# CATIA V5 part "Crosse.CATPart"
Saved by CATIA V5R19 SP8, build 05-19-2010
Part number: Part2
Bounding box of the stored display mesh (mm): x -6.372 to 6.628, y -5 to 5, z -3.329 to 3.329
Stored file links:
  F:\Projet3\Crosse.CATPart
  F:\Projet3\Produit1.CATProduct
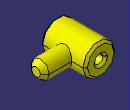
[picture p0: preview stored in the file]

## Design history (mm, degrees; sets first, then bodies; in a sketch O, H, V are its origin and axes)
Parameters
  Longueur = 10 mm
Body1 (main body)
  Sketch1 on yz-plane, origin (0, 0, 0), H (0, 1, 0), V (0, 0, 1)
    circle A1 centre (0, 0) radius 2
    radius A1 = 2 {= Longueur *0.2}
  Pad1: profile Sketch1, direction (1, 0, 0), length 6.628 {= Longueur *0.6628}
  Chamfer1: length 1 {= Longueur *0.1}, angle 45, on edge [face of Pad1 from Sketch1.A1 | end face of Pad1]
  Sketch2 on zx-plane, origin (0, 0, 0), H (-1, 0, 0), V (0, 0, 1)
    arc A1 centre (2.8723, 0) radius 3.5 from (0, 2) to (0, -2) ccw
    point P2 (-0.6277, 0)
    point P3 (0, 2)
    point P4 (0, -2)
    reference projected line E1 (0, -2) -> (0, 2) from edge [start face of Pad1 | face of Pad1 from Sketch1.A1]
    reference projected line E2 (0, -2) -> (0, 2) from edge [start face of Pad1 | face of Pad1 from Sketch1.A1]
    distance P3 P4 = 4 {= Longueur *0.4}
    distance P4 H = 2 {= Longueur *0.2}
    radius A1 = 3.5 {= Longueur *0.35}
    coincidence: A1 P2, P2 H, P3 E1, P4 E2
  Pocket1: profile Sketch2, direction (0, -1, 0), length 8 {= Longueur *0.8}, mirrored extent
  Point1: (0 {= Longueur *0}, 5 {= Longueur *0.5}, 0 {= Longueur *0})
  Plane1: type OffsetPt, RefPlane zx-plane, RefPoint Point1
  Sketch3 on Plane1, origin (0, 5, 0), H (-1, 0, 0), V (0, 0, 1)
    circle A1 centre (2.8723, 0) radius 3.5
    reference projected arc E1 centre (2.8723, 0) radius 3.5 from (0, 2) to (0, -2) ccw from edge [face of Pad1 from Sketch1.A1 | face of Pocket1 from Sketch2.A1]
    coincidence: A1 E1
  Pad2: profile Sketch3, direction (0, -1, 0), length 10 {= Longueur *1}
  Sketch4 on start face of Pad2, origin (0, 5, 0), H (-1, 0, 0), V (0, 0, 1)
    circle A1 centre (2.8723, 0) radius 1
    reference projected circle E1 centre (2.8723, 0) radius 3.5 from edge [face of Pad2 from Sketch3.A1 | start face of Pad2]
    radius A1 = 1 {= Longueur *0.1}
    concentricity: A1 E1
  Pocket2: profile Sketch4, direction (0, -1, 0), up to end face of Pad2, offset 0 {= Longueur *0}
  Thread1: diameter 2.2 {= Longueur *0.22}, depth 10 {= Longueur *1}, pitch 1 {= Longueur *0.1}, on face of Pocket2 from Sketch4.A1, from end face of Pad2
  Chamfer2: length 0.5 {= Longueur *0.05}, angle 45, on edge [end face of Pad2 | face of Pad2 from Sketch3.A1]
  Chamfer3: length 0.5 {= Longueur *0.05}, angle 45, on edge [face of Pad2 from Sketch3.A1 | start face of Pad2]
  Chamfer4: length 0.5 {= Longueur *0.05}, angle 45, on edge [face of Pocket2 from Sketch4.A1 | end face of Pad2]
  Chamfer5: length 0.5 {= Longueur *0.05}, angle 45, on edge [start face of Pad2 | face of Pocket2 from Sketch4.A1]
